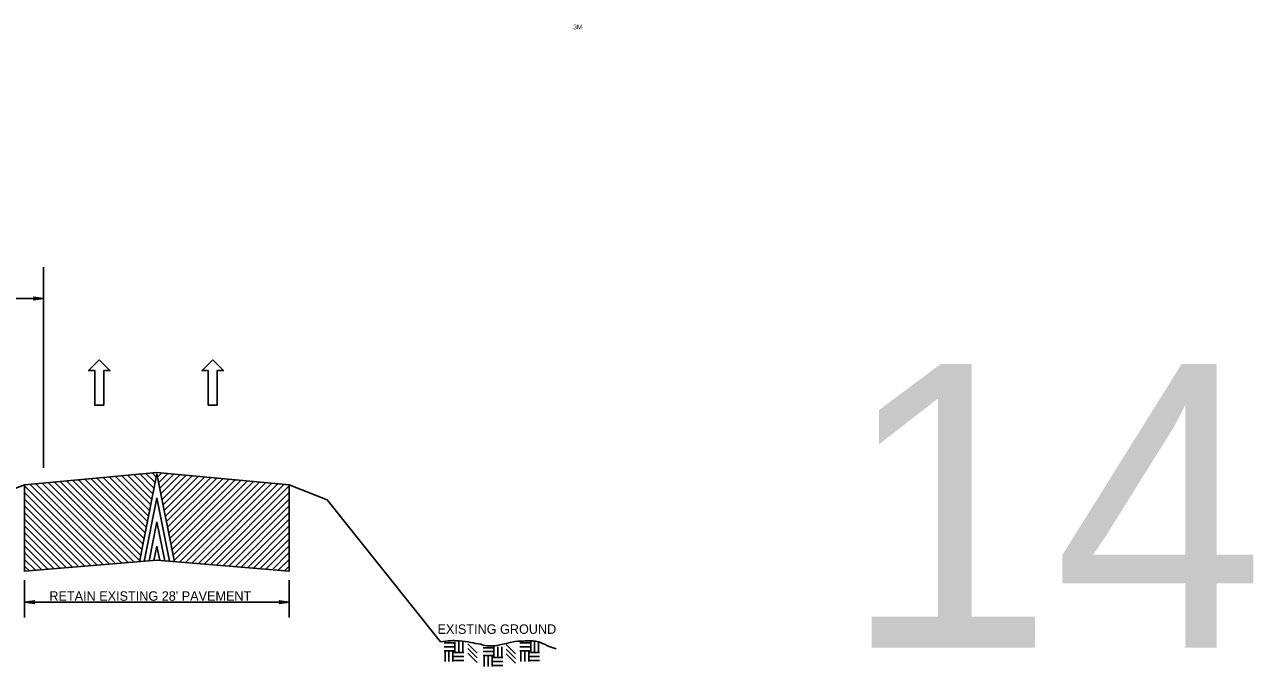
# Model space of a CAD drawing. Extents: x 2003207 to 2014043, y 843846 to 860154.
# Drawn here: x 2013913.3 to 2014043.2, y 844481.5 to 844549.4 of the extents above; entities that cross this region are included whole.
import ezdxf

# ---------------------------------------------------------------- set-up
doc = ezdxf.new("R2010")
doc.units = 0
for name, color, linetype in [('RD_EX_Road', 7, 'Continuous'), ('RD_SHT_TX', 7, 'Continuous'), ('RD_TX_TypSect', 7, 'Continuous'), ('RD_XS_ExGround', 7, 'Continuous')]:
    doc.layers.add(name, color=color, linetype=linetype)

msp = doc.modelspace()

# ---------------------------------------------------------------- linework, layer by layer
at = {"layer": 'RD_EX_Road'}
for p, q in [((2013927.26, 844502.02), (2013913.26, 844500.71)), ((2013922.22, 844501.54), (2013926.36, 844497.4)), ((2013922.86, 844501.61), (2013926.48, 844497.99)), ((2013923.51, 844501.67), (2013926.6, 844498.58)), ((2013924.16, 844501.73), (2013926.72, 844499.16)), ((2013924.8, 844501.79), (2013926.84, 844499.75)), ((2013927.26, 844501.88), (2013925.4, 844492.56)), ((2013925.45, 844501.85), (2013926.95, 844500.34)), ((2013926.09, 844501.91), (2013927.07, 844500.93)), ((2013926.74, 844501.97), (2013927.19, 844501.52)), ((2013927.26, 844502.02), (2013941.26, 844500.71)), ((2013927.26, 844501.88), (2013929.13, 844492.56)), ((2013927.78, 844501.97), (2013927.33, 844501.52)), ((2013928.43, 844501.91), (2013927.45, 844500.93)), ((2013929.07, 844501.85), (2013927.57, 844500.34)), ((2013929.72, 844501.79), (2013927.69, 844499.75)), ((2013930.37, 844501.73), (2013927.8, 844499.16)), ((2013931.01, 844501.67), (2013927.92, 844498.58)), ((2013931.66, 844501.61), (2013928.04, 844497.99)), ((2013932.31, 844501.54), (2013928.16, 844497.4)), ((2013913.26, 844491.54), (2013913.26, 844500.71)), ((2013913.26, 844500.6), (2013921.61, 844492.25)), ((2013913.81, 844500.76), (2013922.26, 844492.31)), ((2013914.46, 844500.82), (2013922.91, 844492.36)), ((2013915.12, 844500.86), (2013915.26, 844500.72)), ((2013915.26, 844500.72), (2013923.56, 844492.42)), ((2013915.76, 844500.93), (2013924.22, 844492.47)), ((2013916.41, 844500.99), (2013924.87, 844492.53)), ((2013917.04, 844501.06), (2013925.42, 844492.68)), ((2013917.69, 844501.12), (2013925.54, 844493.27)), ((2013918.34, 844501.18), (2013925.66, 844493.86)), ((2013918.98, 844501.24), (2013925.77, 844494.45)), ((2013919.63, 844501.3), (2013925.89, 844495.04)), ((2013920.28, 844501.36), (2013926.01, 844495.63)), ((2013920.92, 844501.42), (2013926.13, 844496.22)), ((2013921.57, 844501.48), (2013926.25, 844496.81)), ((2013932.95, 844501.48), (2013928.28, 844496.81)), ((2013933.6, 844501.42), (2013928.39, 844496.22)), ((2013934.25, 844501.36), (2013928.51, 844495.63)), ((2013934.89, 844501.3), (2013928.63, 844495.04)), ((2013935.54, 844501.24), (2013928.75, 844494.45)), ((2013936.18, 844501.18), (2013928.86, 844493.86)), ((2013936.83, 844501.12), (2013928.98, 844493.27)), ((2013937.48, 844501.06), (2013929.1, 844492.68)), ((2013938.11, 844500.99), (2013929.65, 844492.53)), ((2013938.77, 844500.93), (2013930.3, 844492.47)), ((2013939.42, 844500.88), (2013930.96, 844492.42)), ((2013940.06, 844500.82), (2013931.61, 844492.36)), ((2013940.71, 844500.76), (2013932.26, 844492.31)), ((2013941.26, 844500.6), (2013932.92, 844492.25)), ((2013941.26, 844491.54), (2013941.26, 844500.71)), ((2013913.26, 844499.89), (2013920.95, 844492.2)), ((2013913.26, 844499.19), (2013920.3, 844492.15)), ((2013927.26, 844499.33), (2013925.92, 844492.6)), ((2013927.26, 844499.33), (2013928.6, 844492.61)), ((2013941.26, 844499.89), (2013933.57, 844492.2)), ((2013941.26, 844499.19), (2013934.22, 844492.15)), ((2013913.26, 844498.48), (2013919.65, 844492.09)), ((2013913.26, 844497.77), (2013919, 844492.04)), ((2013941.26, 844498.48), (2013934.87, 844492.09)), ((2013941.26, 844497.77), (2013935.53, 844492.04)), ((2013913.26, 844497.06), (2013918.34, 844491.98)), ((2013913.26, 844496.36), (2013917.69, 844491.93)), ((2013927.26, 844496.78), (2013926.43, 844492.65)), ((2013927.26, 844496.78), (2013928.09, 844492.65)), ((2013941.26, 844497.06), (2013936.18, 844491.98)), ((2013941.26, 844496.36), (2013936.83, 844491.93)), ((2013913.26, 844495.65), (2013917.04, 844491.87)), ((2013941.26, 844495.65), (2013937.48, 844491.87)), ((2013913.26, 844494.94), (2013916.38, 844491.82)), ((2013913.26, 844494.24), (2013915.73, 844491.77)), ((2013927.26, 844494.23), (2013926.95, 844492.69)), ((2013927.26, 844494.23), (2013927.57, 844492.69)), ((2013941.26, 844494.94), (2013938.14, 844491.82)), ((2013941.26, 844494.24), (2013938.79, 844491.77)), ((2013913.26, 844493.53), (2013915.08, 844491.71)), ((2013913.26, 844492.82), (2013914.43, 844491.66)), ((2013927.26, 844492.73), (2013913.26, 844491.56)), ((2013927.26, 844492.73), (2013941.26, 844491.56)), ((2013941.26, 844493.53), (2013939.44, 844491.71)), ((2013941.26, 844492.82), (2013940.1, 844491.66)), ((2013913.26, 844492.11), (2013913.77, 844491.6)), ((2013941.26, 844492.11), (2013940.75, 844491.6))]:
    msp.add_line(p, q, dxfattribs=at)
at = {"layer": 'RD_TX_TypSect'}
for p, q in [((2013915.26, 844502.51), (2013915.26, 844523.72)), ((2013875.26, 844520.41), (2013915.26, 844520.41)), ((2013913.26, 844490.6), (2013913.26, 844486.66)), ((2013941.26, 844490.6), (2013941.26, 844486.66)), ((2013913.26, 844488.29), (2013941.26, 844488.29))]:
    msp.add_line(p, q, dxfattribs=at)
for points in [[(2013915.26, 844520.41), (2013914.22, 844520.26), (2013914.38, 844520.41), (2013914.22, 844520.56)], [(2013921.64, 844509.11), (2013920.68, 844509.11), (2013920.68, 844512.78), (2013920.03, 844512.78), (2013921.16, 844513.91), (2013922.29, 844512.78), (2013921.64, 844512.78)], [(2013933.64, 844509.11), (2013932.68, 844509.11), (2013932.68, 844512.78), (2013932.03, 844512.78), (2013933.16, 844513.91), (2013934.29, 844512.78), (2013933.64, 844512.78)], [(2013913.26, 844488.29), (2013914.3, 844488.44), (2013914.14, 844488.29), (2013914.3, 844488.14)], [(2013941.26, 844488.29), (2013940.22, 844488.14), (2013940.38, 844488.29), (2013940.22, 844488.44)]]:
    msp.add_lwpolyline(points, close=True, dxfattribs=at)
at = {"layer": 'RD_XS_ExGround'}
for p, q in [((2013913.26, 844500.71), (2013911.26, 844499.91)), ((2013941.26, 844500.71), (2013945.26, 844499.11)), ((2013945.26, 844499.11), (2013957.26, 844484.11)), ((2013958.67, 844483.99), (2013957.63, 844483.99)), ((2013958.67, 844483.58), (2013957.63, 844483.58)), ((2013958.77, 844484.09), (2013958.77, 844483.05)), ((2013959.19, 844484.09), (2013959.19, 844483.05)), ((2013959.6, 844484.09), (2013959.6, 844483.05)), ((2013961.13, 844482.9), (2013960.13, 844483.9)), ((2013961.13, 844482.4), (2013960.13, 844483.4)), ((2013962.81, 844483.47), (2013961.77, 844483.47)), ((2013962.91, 844483.57), (2013962.91, 844482.53)), ((2013963.32, 844483.57), (2013963.32, 844482.53)), ((2013963.74, 844483.57), (2013963.74, 844482.53)), ((2013965.19, 844482.83), (2013964.19, 844483.83)), ((2013965.19, 844482.33), (2013964.19, 844483.33)), ((2013966.7, 844483.99), (2013965.66, 844483.99)), ((2013966.7, 844483.57), (2013965.66, 844483.57)), ((2013966.8, 844484.08), (2013966.8, 844483.04)), ((2013967.21, 844484.08), (2013967.21, 844483.04)), ((2013967.63, 844484.08), (2013967.63, 844483.04)), ((2013958.67, 844483.16), (2013957.63, 844483.16)), ((2013957.74, 844483.06), (2013957.74, 844482.01)), ((2013958.15, 844483.06), (2013958.15, 844482.01)), ((2013958.57, 844483.06), (2013958.57, 844482.01)), ((2013959.72, 844482.95), (2013958.67, 844482.95)), ((2013959.72, 844482.53), (2013958.67, 844482.53)), ((2013959.72, 844482.12), (2013958.67, 844482.12)), ((2013961.13, 844481.9), (2013960.13, 844482.9)), ((2013962.81, 844483.06), (2013961.77, 844483.06)), ((2013962.81, 844482.64), (2013961.77, 844482.64)), ((2013961.87, 844482.54), (2013961.87, 844481.49)), ((2013962.29, 844482.54), (2013962.29, 844481.49)), ((2013962.71, 844482.54), (2013962.71, 844481.49)), ((2013963.85, 844482.43), (2013962.81, 844482.43)), ((2013965.19, 844481.83), (2013964.19, 844482.83)), ((2013966.7, 844483.15), (2013965.66, 844483.15)), ((2013965.76, 844483.05), (2013965.76, 844482.01)), ((2013966.18, 844483.05), (2013966.18, 844482.01)), ((2013966.6, 844483.05), (2013966.6, 844482.01)), ((2013967.74, 844482.95), (2013966.7, 844482.95)), ((2013967.74, 844482.53), (2013966.7, 844482.53)), ((2013967.74, 844482.11), (2013966.7, 844482.11)), ((2013963.85, 844482.02), (2013962.81, 844482.02)), ((2013963.85, 844481.6), (2013962.81, 844481.6))]:
    msp.add_line(p, q, dxfattribs=at)
msp.add_lwpolyline([(2013969.49, 844483.37), (2013969.27, 844483.41), (2013969.05, 844483.48), (2013968.75, 844483.59), (2013968.5, 844483.7), (2013968.28, 844483.85), (2013968.1, 844483.89), (2013967.84, 844484.03), (2013967.62, 844484.11), (2013967.29, 844484.18), (2013967.03, 844484.21), (2013966.74, 844484.21), (2013966.41, 844484.21), (2013966.23, 844484.21), (2013966.05, 844484.18), (2013965.83, 844484.18), (2013965.61, 844484.18), (2013965.42, 844484.18), (2013965.13, 844484.14), (2013964.95, 844484.11), (2013964.62, 844484.03), (2013964.33, 844483.96), (2013964.03, 844483.89), (2013963.85, 844483.85), (2013963.52, 844483.78), (2013963.23, 844483.7), (2013963.01, 844483.67), (2013962.82, 844483.67), (2013962.61, 844483.67), (2013962.39, 844483.67), (2013962.17, 844483.67), (2013961.95, 844483.7), (2013961.76, 844483.74), (2013961.51, 844483.85), (2013961.25, 844483.89), (2013960.96, 844483.92), (2013960.7, 844484), (2013960.45, 844484.03), (2013960.15, 844484.11), (2013959.86, 844484.14), (2013959.57, 844484.18), (2013959.24, 844484.21), (2013958.94, 844484.21), (2013958.73, 844484.25), (2013958.54, 844484.25), (2013958.36, 844484.21), (2013958.07, 844484.21), (2013957.81, 844484.18), (2013957.55, 844484.14), (2013957.26, 844484.11)], dxfattribs=at)

# ---------------------------------------------------------------- texts
at = {"layer": 'RD_SHT_TX'}
for s, height, p in [('3M', 0.5, (2013971.3, 844548.87)), ('14', 30, (2013999.79, 844483.49))]:
    msp.add_text(s, height=height, dxfattribs=at).set_placement(p)
at = {"layer": 'RD_TX_TypSect'}
for s, p in [("RETAIN EXISTING 28' PAVEMENT", (2013915.88, 844488.44)), ('EXISTING GROUND', (2013956.94, 844484.94))]:
    msp.add_text(s, height=1, dxfattribs=at).set_placement(p)

doc.saveas('drawing.dxf')
